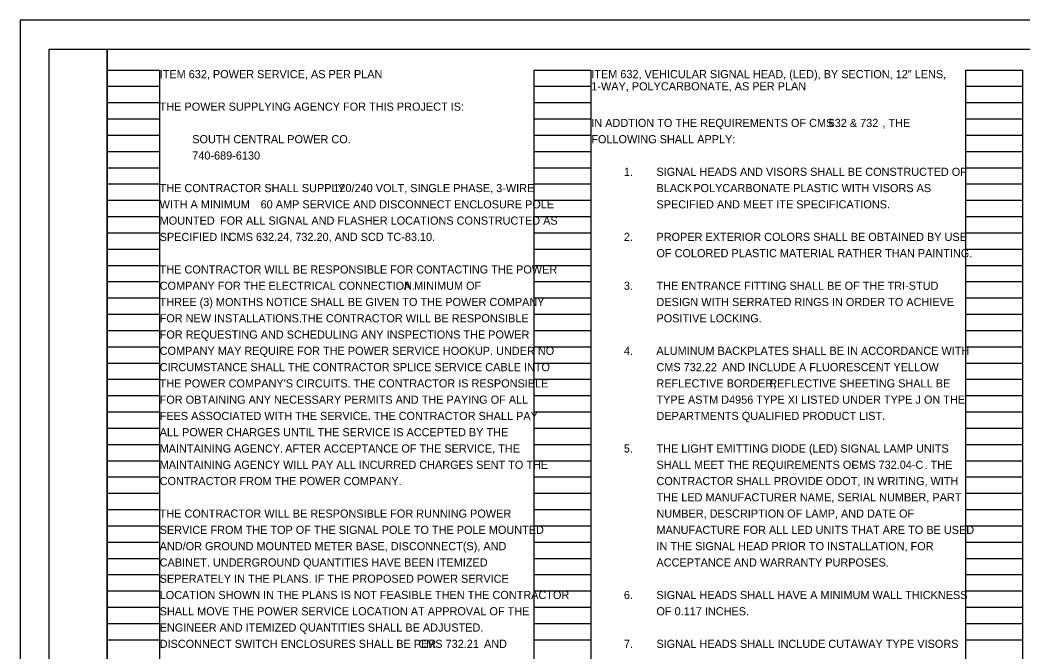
# Model space of a CAD drawing. Extents: x 0 to 34, y 0 to 22.
# Drawn here: x 0 to 17.24, y 11.13 to 22 of the extents above; entities that cross this region are included whole.
import ezdxf

# ---------------------------------------------------------------- set-up
doc = ezdxf.new("R2010")
doc.units = 0
for name, color, linetype in [('SH_Border', 7, 'Continuous'), ('SH_Cut_Line', 7, 'Continuous'), ('SH_Data', 7, 'Continuous'), ('SH_Text', 7, 'Continuous')]:
    doc.layers.add(name, color=color, linetype=linetype)

msp = doc.modelspace()

# ---------------------------------------------------------------- linework, layer by layer
at = {"layer": 'SH_Border'}
for points in [[(0.5, 21.5), (1.5, 21.5), (1.5, 0.5), (0.5, 0.5)], [(1.5, 21.5), (33.5, 21.5), (33.5, 0.5), (1.5, 0.5)]]:
    msp.add_lwpolyline(points, close=True, dxfattribs=at)
at = {"layer": 'SH_Cut_Line'}
msp.add_lwpolyline([(0, 0), (34, 0), (34, 22), (0, 22)], close=True, dxfattribs=at)
at = {"layer": 'SH_Data'}
for p, q in [((1.5, 0.98), (1.5, 21.14)), ((1.5, 21.14), (2.4, 21.14)), ((2.4, 0.98), (2.4, 21.14)), ((8.84, 0.98), (8.84, 21.14)), ((8.84, 21.14), (9.82, 21.14)), ((9.82, 0.98), (9.82, 21.14)), ((16.26, 0.98), (16.26, 21.14)), ((16.26, 21.14), (17.24, 21.14)), ((17.24, 0.98), (17.24, 21.14)), ((1.5, 20.86), (2.4, 20.86)), ((8.84, 20.86), (9.82, 20.86)), ((16.26, 20.86), (17.24, 20.86)), ((1.5, 20.58), (2.4, 20.58)), ((8.84, 20.58), (9.82, 20.58)), ((16.26, 20.58), (17.24, 20.58)), ((1.5, 20.3), (2.4, 20.3)), ((8.84, 20.3), (9.82, 20.3)), ((16.26, 20.3), (17.24, 20.3)), ((1.5, 20.02), (2.4, 20.02)), ((8.84, 20.02), (9.82, 20.02)), ((16.26, 20.02), (17.24, 20.02)), ((1.5, 19.74), (2.4, 19.74)), ((8.84, 19.74), (9.82, 19.74)), ((16.26, 19.74), (17.24, 19.74)), ((1.5, 19.46), (2.4, 19.46)), ((8.84, 19.46), (9.82, 19.46)), ((16.26, 19.46), (17.24, 19.46)), ((1.5, 19.18), (2.4, 19.18)), ((8.84, 19.18), (9.82, 19.18)), ((16.26, 19.18), (17.24, 19.18)), ((1.5, 18.9), (2.4, 18.9)), ((8.84, 18.9), (9.82, 18.9)), ((16.26, 18.9), (17.24, 18.9)), ((1.5, 18.62), (2.4, 18.62)), ((8.84, 18.62), (9.82, 18.62)), ((16.26, 18.62), (17.24, 18.62)), ((1.5, 18.34), (2.4, 18.34)), ((8.84, 18.34), (9.82, 18.34)), ((16.26, 18.34), (17.24, 18.34)), ((1.5, 18.06), (2.4, 18.06)), ((8.84, 18.06), (9.82, 18.06)), ((16.26, 18.06), (17.24, 18.06)), ((1.5, 17.78), (2.4, 17.78)), ((8.84, 17.78), (9.82, 17.78)), ((16.26, 17.78), (17.24, 17.78)), ((1.5, 17.5), (2.4, 17.5)), ((8.84, 17.5), (9.82, 17.5)), ((16.26, 17.5), (17.24, 17.5)), ((1.5, 17.22), (2.4, 17.22)), ((8.84, 17.22), (9.82, 17.22)), ((16.26, 17.22), (17.24, 17.22)), ((1.5, 16.94), (2.4, 16.94)), ((8.84, 16.94), (9.82, 16.94)), ((16.26, 16.94), (17.24, 16.94)), ((1.5, 16.66), (2.4, 16.66)), ((8.84, 16.66), (9.82, 16.66)), ((16.26, 16.66), (17.24, 16.66)), ((1.5, 16.38), (2.4, 16.38)), ((8.84, 16.38), (9.82, 16.38)), ((16.26, 16.38), (17.24, 16.38)), ((1.5, 16.1), (2.4, 16.1)), ((8.84, 16.1), (9.82, 16.1)), ((16.26, 16.1), (17.24, 16.1)), ((1.5, 15.82), (2.4, 15.82)), ((8.84, 15.82), (9.82, 15.82)), ((16.26, 15.82), (17.24, 15.82)), ((1.5, 15.54), (2.4, 15.54)), ((8.84, 15.54), (9.82, 15.54)), ((16.26, 15.54), (17.24, 15.54)), ((1.5, 15.26), (2.4, 15.26)), ((8.84, 15.26), (9.82, 15.26)), ((16.26, 15.26), (17.24, 15.26)), ((1.5, 14.98), (2.4, 14.98)), ((8.84, 14.98), (9.82, 14.98)), ((16.26, 14.98), (17.24, 14.98)), ((1.5, 14.7), (2.4, 14.7)), ((8.84, 14.7), (9.82, 14.7)), ((16.26, 14.7), (17.24, 14.7)), ((1.5, 14.42), (2.4, 14.42)), ((8.84, 14.42), (9.82, 14.42)), ((16.26, 14.42), (17.24, 14.42)), ((1.5, 14.14), (2.4, 14.14)), ((8.84, 14.14), (9.82, 14.14)), ((16.26, 14.14), (17.24, 14.14)), ((1.5, 13.86), (2.4, 13.86)), ((8.84, 13.86), (9.82, 13.86)), ((16.26, 13.86), (17.24, 13.86)), ((1.5, 13.58), (2.4, 13.58)), ((8.84, 13.58), (9.82, 13.58)), ((16.26, 13.58), (17.24, 13.58)), ((1.5, 13.3), (2.4, 13.3)), ((8.84, 13.3), (9.82, 13.3)), ((16.26, 13.3), (17.24, 13.3)), ((1.5, 13.02), (2.4, 13.02)), ((8.84, 13.02), (9.82, 13.02)), ((16.26, 13.02), (17.24, 13.02)), ((1.5, 12.74), (2.4, 12.74)), ((8.84, 12.74), (9.82, 12.74)), ((16.26, 12.74), (17.24, 12.74)), ((1.5, 12.46), (2.4, 12.46)), ((8.84, 12.46), (9.82, 12.46)), ((16.26, 12.46), (17.24, 12.46)), ((1.5, 12.18), (2.4, 12.18)), ((8.84, 12.18), (9.82, 12.18)), ((16.26, 12.18), (17.24, 12.18)), ((1.5, 11.9), (2.4, 11.9)), ((8.84, 11.9), (9.82, 11.9)), ((16.26, 11.9), (17.24, 11.9)), ((1.5, 11.62), (2.4, 11.62)), ((8.84, 11.62), (9.82, 11.62)), ((16.26, 11.62), (17.24, 11.62)), ((1.5, 11.34), (2.4, 11.34)), ((8.84, 11.34), (9.82, 11.34)), ((16.26, 11.34), (17.24, 11.34))]:
    msp.add_line(p, q, dxfattribs=at)

# ---------------------------------------------------------------- texts
at = {"layer": 'SH_Text'}
for s, p in [('ITEM 632, POWER SERVICE, AS PER PLAN', (2.4, 21)), ('ITEM 632, VEHICULAR SIGNAL HEAD, (LED), BY SECTION, 12" LENS,', (9.82, 21)), ('1-WAY, POLYCARBONATE, AS PER PLAN', (9.82, 20.79)), ('THE POWER SUPPLYING AGENCY FOR THIS PROJECT IS:', (2.4, 20.44)), ('IN ADDTION TO THE REQUIREMENTS OF CMS ', (9.82, 20.16)), ('632 & 732', (13.9, 20.16)), (', THE', (14.825, 20.16)), ('SOUTH CENTRAL POWER CO.', (2.96, 19.88)), ('FOLLOWING SHALL APPLY:', (9.82, 19.88)), ('740-689-6130', (2.96, 19.6)), ('1. ', (10.38, 19.32)), ('SIGNAL HEADS AND VISORS SHALL BE CONSTRUCTED OF', (10.94, 19.32)), ('THE CONTRACTOR SHALL SUPPLY ', (2.4, 19.04)), ('120/240 VOLT, SINGLE PHASE, 3-WIRE', (5.386, 19.04)), ('BLACK', (10.94, 19.04)), (' POLYCARBONATE PLASTIC WITH VISORS AS', (11.521, 19.04)), ('WITH A MINIMUM ', (2.4, 18.76)), ('60 AMP SERVICE AND DISCONNECT ENCLOSURE POLE', (4.135, 18.76)), ('SPECIFIED AND MEET ITE SPECIFICATIONS.', (10.94, 18.76)), ('MOUNTED', (2.4, 18.48)), (' FOR ALL SIGNAL AND FLASHER LOCATIONS CONSTRUCTED AS', (3.385, 18.48)), ('SPECIFIED IN ', (2.4, 18.2)), ('CMS 632.24, 732.20, AND SCD TC-83.10.', (3.587, 18.2)), ('2. ', (10.38, 18.2)), ('PROPER EXTERIOR COLORS SHALL BE OBTAINED BY USE', (10.94, 18.2)), ('OF COLORED PLASTIC MATERIAL RATHER THAN PAINTING.', (10.94, 17.92)), ('THE CONTRACTOR WILL BE RESPONSIBLE FOR CONTACTING THE POWER', (2.4, 17.64)), ('COMPANY FOR THE ELECTRICAL CONNECTION. ', (2.4, 17.36)), ('A MINIMUM OF ', (6.596, 17.36)), ('3. ', (10.38, 17.36)), ('THE ENTRANCE FITTING SHALL BE OF THE TRI-STUD', (10.94, 17.36)), ('THREE (3) MONTHS NOTICE SHALL BE GIVEN TO THE POWER COMPANY', (2.4, 17.08)), ('DESIGN WITH SERRATED RINGS IN ORDER TO ACHIEVE', (10.94, 17.08)), ('FOR NEW INSTALLATIONS.', (2.4, 16.8)), (' THE CONTRACTOR WILL BE RESPONSIBLE', (4.779, 16.8)), ('POSITIVE LOCKING.', (10.94, 16.8)), ('FOR REQUESTING AND SCHEDULING ANY INSPECTIONS THE POWER', (2.4, 16.52)), ('COMPANY MAY REQUIRE FOR THE POWER SERVICE HOOKUP. UNDER NO', (2.4, 16.24)), ('4.', (10.38, 16.24)), ('ALUMINUM BACKPLATES SHALL BE IN ACCORDANCE WITH', (10.94, 16.24)), ('CIRCUMSTANCE SHALL THE CONTRACTOR SPLICE SERVICE CABLE INTO', (2.4, 15.96)), ('CMS 732.22', (10.94, 15.96)), (' AND INCLUDE A FLUORESCENT YELLOW', (12.017, 15.96)), ("THE POWER COMPANY'S CIRCUITS. THE CONTRACTOR IS RESPONSIBLE", (2.4, 15.68)), ('REFLECTIVE BORDER, ', (10.94, 15.68)), ('REFLECTIVE SHEETING SHALL BE', (12.88, 15.68)), ('FOR OBTAINING ANY NECESSARY PERMITS AND THE PAYING OF ALL', (2.4, 15.4)), ('TYPE ASTM D4956 TYPE XI LISTED UNDER TYPE J ON THE', (10.94, 15.4)), ('FEES ASSOCIATED WITH THE SERVICE. THE CONTRACTOR SHALL PAY', (2.4, 15.12)), ('DEPARTMENTS QUALIFIED PRODUCT LIST.', (10.94, 15.12)), ('ALL POWER CHARGES UNTIL THE SERVICE IS ACCEPTED BY THE ', (2.4, 14.84)), ('MAINTAINING AGENCY. ', (2.4, 14.56)), ('AFTER ACCEPTANCE OF THE SERVICE, THE', (4.558, 14.56)), ('5.', (10.38, 14.56)), ('THE LIGHT EMITTING DIODE (LED) SIGNAL LAMP UNITS', (10.94, 14.56)), ('MAINTAINING AGENCY WILL PAY ALL INCURRED CHARGES SENT TO THE', (2.4, 14.28)), ('SHALL MEET THE REQUIREMENTS OF ', (10.94, 14.28)), ('CMS 732.04-C', (14.29, 14.28)), ('. THE', (15.549, 14.28)), ('CONTRACTOR FROM THE POWER COMPANY.', (2.4, 14)), ('CONTRACTOR SHALL PROVIDE ODOT, IN WRITING, WITH', (10.94, 14)), ('THE LED MANUFACTURER NAME, SERIAL NUMBER, PART', (10.94, 13.72)), ('THE CONTRACTOR WILL BE RESPONSIBLE FOR RUNNING POWER', (2.4, 13.44)), ('NUMBER, DESCRIPTION OF LAMP, AND DATE OF', (10.94, 13.44)), ('SERVICE FROM THE TOP OF THE SIGNAL POLE TO THE POLE MOUNTED', (2.4, 13.16)), ('MANUFACTURE FOR ALL LED UNITS THAT ARE TO BE USED', (10.94, 13.16)), ('AND/OR GROUND MOUNTED METER BASE, DISCONNECT(S), AND', (2.4, 12.88)), ('IN THE SIGNAL HEAD PRIOR TO INSTALLATION, FOR', (10.94, 12.88)), ('CABINET. UNDERGROUND QUANTITIES HAVE BEEN ITEMIZED', (2.4, 12.6)), ('ACCEPTANCE AND WARRANTY PURPOSES.', (10.94, 12.6)), ('SEPERATELY IN THE PLANS. IF THE PROPOSED POWER SERVICE ', (2.4, 12.32)), ('LOCATION SHOWN IN THE PLANS IS NOT FEASIBLE THEN THE CONTRACTOR', (2.4, 12.04)), ('6.', (10.38, 12.04)), ('SIGNAL HEADS SHALL HAVE A MINIMUM WALL THICKNESS', (10.94, 12.04)), ('SHALL MOVE THE POWER SERVICE LOCATION AT APPROVAL OF THE', (2.4, 11.76)), ('OF 0.117 INCHES.', (10.94, 11.76)), ('ENGINEER AND ITEMIZED QUANTITIES SHALL BE ADJUSTED.', (2.4, 11.48)), ('DISCONNECT SWITCH ENCLOSURES SHALL BE PER ', (2.4, 11.2)), ('CMS 732.21', (6.847, 11.2)), (' AND', (7.924, 11.2)), ('7.', (10.38, 11.2)), ('SIGNAL HEADS SHALL INCLUDE CUTAWAY TYPE VISORS', (10.94, 11.2))]:
    msp.add_text(s, height=0.14, dxfattribs=at).set_placement(p)

doc.saveas('drawing.dxf')
